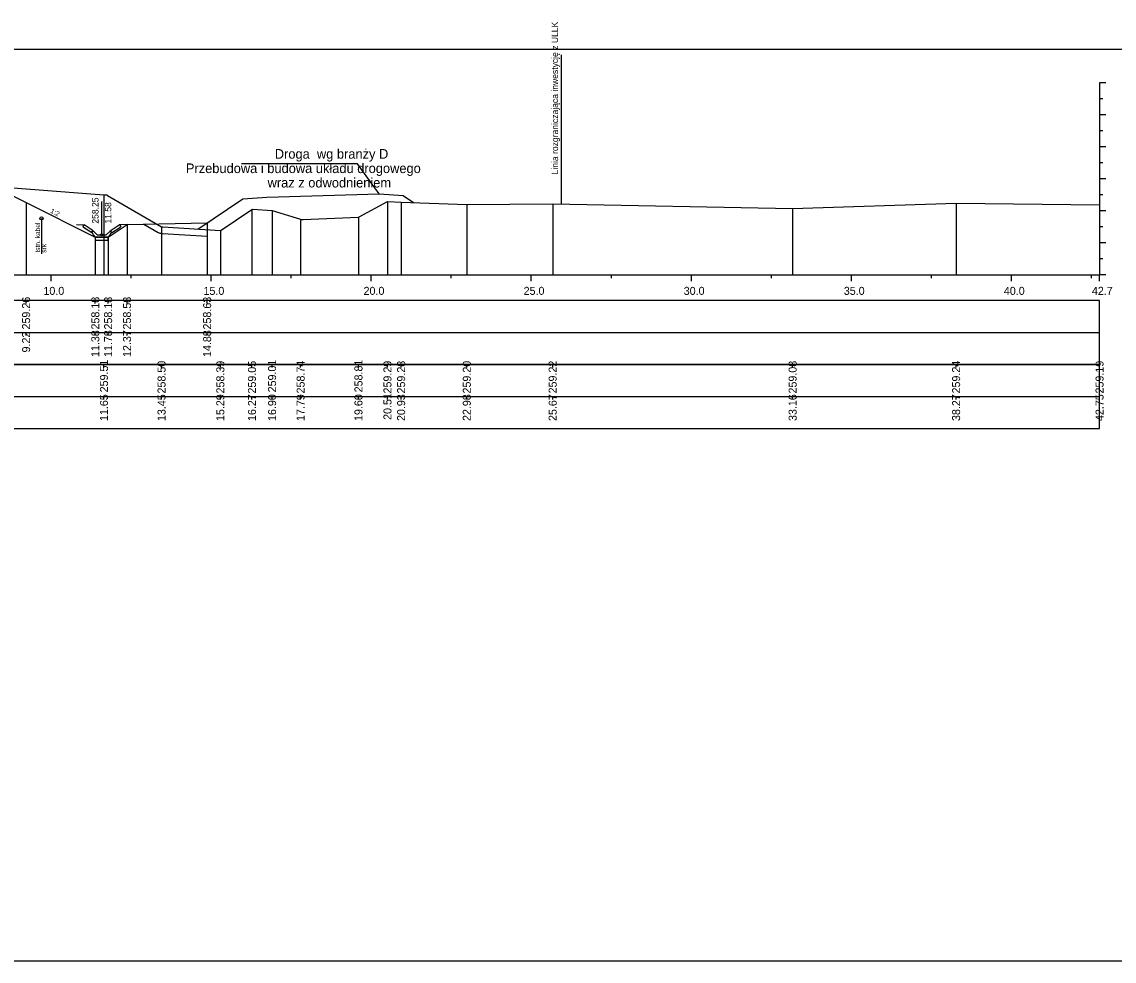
# Model space of a CAD drawing. Extents: x 6516023 to 6560129, y 5513077 to 5529206.
# Drawn here: x 6517319.3 to 6517353.42, y 5514518.16 to 5514547.51 of the extents above; entities that cross this region are included whole.
import ezdxf

# ---------------------------------------------------------------- set-up
doc = ezdxf.new("R2010")
doc.units = 0
for name, color, linetype in [('IR_default', 7, 'Continuous'), ('TOR_PRZEK_P-inne branze', 7, 'Continuous'), ('TOR_PRZEK_P-kable', 7, 'Continuous'), ('TOR_PRZEK_P-odwodnienie', 7, 'Continuous'), ('TOR_PRZEK_P-opisy', 7, 'Continuous'), ('TOR_PRZEK_P-tabelka istniejace', 7, 'Continuous'), ('TOR_PRZEK_P-tabelka projektowane', 7, 'Continuous'), ('TOR_PRZEK_P-teren istniejacy', 7, 'Continuous'), ('TOR_PRZEK_P-uklad odniesienia', 7, 'Continuous'), ('TOR_PRZEK_P-warstwa ochronna II', 7, 'Continuous'), ('TOR_PS_T-granica PKP-projektowana', 7, 'Continuous'), ('TOR_PS_T-skarpy projektowane', 7, 'Continuous'), ('TOR_RAMKI-ramka+tabelka 1', 7, 'Continuous')]:
    doc.layers.add(name, color=color, linetype=linetype)

msp = doc.modelspace()

# ---------------------------------------------------------------- linework, layer by layer
at = {"layer": 'IR_default'}
msp.add_lwpolyline([(6517303.963, 5514543.245), (6517307.463, 5514543.246), (6517308.463, 5514543.246), (6517311.963, 5514543.246), (6517312.513, 5514543.247), (6517316.013, 5514543.247), (6517317.359, 5514542.35), (6517318.563, 5514542.302), (6517319.433, 5514541.867), (6517321.593, 5514540.787), (6517321.993, 5514540.787), (6517322.586, 5514541.181), (6517325.088, 5514541.231)], dxfattribs=at)
at = {"layer": 'TOR_PRZEK_P-inne branze'}
for p, q in [((6517329.781, 5514543.077), (6517326.157, 5514543.077)), ((6517330.457, 5514542.142), (6517329.781, 5514543.077))]:
    msp.add_line(p, q, dxfattribs=at)
msp.add_lwpolyline([(6517324.795, 5514541.036), (6517326.207, 5514541.977), (6517326.957, 5514542.037), (6517328.707, 5514542.09), (6517330.457, 5514542.142), (6517331.207, 5514542.082), (6517331.532, 5514541.866)], dxfattribs=at)
at = {"layer": 'TOR_PRZEK_P-kable'}
msp.add_line((6517319.915, 5514541.372), (6517319.915, 5514540.262), dxfattribs=at)
msp.add_circle((6517319.915, 5514541.372), 0.05, dxfattribs=at)
at = {"layer": 'TOR_PRZEK_P-odwodnienie'}
for p, q in [((6517321.795, 5514540.857), (6517321.795, 5514541.901)), ((6517321.486, 5514540.916), (6517321.225, 5514541.09)), ((6517321.53, 5514540.983), (6517321.25, 5514541.17)), ((6517321.497, 5514540.933), (6517321.486, 5514540.916)), ((6517321.487, 5514540.952), (6517321.535, 5514540.976)), ((6517321.53, 5514540.983), (6517321.522, 5514540.97)), ((6517321.655, 5514540.857), (6517321.535, 5514540.976)), ((6517321.655, 5514540.857), (6517321.935, 5514540.857)), ((6517321.935, 5514540.857), (6517322.055, 5514540.976)), ((6517322.055, 5514540.976), (6517322.102, 5514540.952)), ((6517322.059, 5514540.983), (6517322.34, 5514541.17)), ((6517322.059, 5514540.983), (6517322.068, 5514540.97)), ((6517322.093, 5514540.933), (6517322.104, 5514540.916)), ((6517322.104, 5514540.916), (6517322.365, 5514541.09)), ((6517321.605, 5514540.787), (6517321.985, 5514540.787))]:
    msp.add_line(p, q, dxfattribs=at)
for points in [[(6517321.003, 5514541.181), (6517321.25, 5514541.17)], [(6517321.2, 5514541.143), (6517321.25, 5514541.17)], [(6517321.2, 5514541.143), (6517321.225, 5514541.09)], [(6517321.522, 5514540.97), (6517321.487, 5514540.952)], [(6517321.535, 5514540.857), (6517321.487, 5514540.952)], [(6517321.487, 5514540.952), (6517321.497, 5514540.933)], [(6517321.605, 5514540.787), (6517321.535, 5514540.857)], [(6517321.985, 5514540.787), (6517322.055, 5514540.857)], [(6517322.055, 5514540.857), (6517322.102, 5514540.952)], [(6517322.068, 5514540.97), (6517322.103, 5514540.952)], [(6517322.103, 5514540.952), (6517322.093, 5514540.933)], [(6517322.586, 5514541.181), (6517322.34, 5514541.17)], [(6517322.39, 5514541.143), (6517322.34, 5514541.17)], [(6517322.39, 5514541.143), (6517322.365, 5514541.09)], [(6517321.593, 5514540.787), (6517321.593, 5514540.787), (6517321.593, 5514540.787), (6517321.593, 5514540.786), (6517321.593, 5514540.787), (6517321.594, 5514540.786), (6517321.593, 5514540.787), (6517321.594, 5514540.787)], [(6517321.594, 5514540.787), (6517321.594, 5514540.788), (6517321.594, 5514540.787), (6517321.594, 5514540.787), (6517321.594, 5514540.787), (6517321.595, 5514540.787), (6517321.594, 5514540.787), (6517321.595, 5514540.788)], [(6517321.995, 5514540.787), (6517321.595, 5514540.787), (6517321.595, 5514540.687), (6517321.995, 5514540.687), (6517321.995, 5514540.787)], [(6517321.994, 5514540.787), (6517321.993, 5514540.788), (6517321.994, 5514540.787), (6517321.993, 5514540.787), (6517321.994, 5514540.787), (6517321.994, 5514540.787), (6517321.994, 5514540.787), (6517321.994, 5514540.788)], [(6517321.993, 5514540.787), (6517321.993, 5514540.787), (6517321.993, 5514540.787), (6517321.993, 5514540.786), (6517321.993, 5514540.787), (6517321.994, 5514540.786), (6517321.993, 5514540.787), (6517321.994, 5514540.787)]]:
    msp.add_lwpolyline(points, dxfattribs=at)
msp.add_circle((6517321.795, 5514540.857), 0.035, dxfattribs=at)
at = {"layer": 'TOR_PRZEK_P-tabelka istniejace'}
for p, q in [((6517321.865, 5514536.706), (6517321.865, 5514536.806)), ((6517323.664, 5514536.706), (6517323.664, 5514536.806)), ((6517325.5, 5514536.706), (6517325.5, 5514536.806)), ((6517326.488, 5514536.706), (6517326.488, 5514536.806)), ((6517327.116, 5514536.706), (6517327.116, 5514536.806)), ((6517328.008, 5514536.706), (6517328.008, 5514536.806)), ((6517329.815, 5514536.706), (6517329.815, 5514536.806)), ((6517330.72, 5514536.706), (6517330.72, 5514536.806)), ((6517331.147, 5514536.706), (6517331.147, 5514536.806)), ((6517333.198, 5514536.706), (6517333.198, 5514536.806)), ((6517335.881, 5514536.706), (6517335.881, 5514536.806)), ((6517343.376, 5514536.706), (6517343.376, 5514536.806)), ((6517348.482, 5514536.706), (6517348.482, 5514536.806)), ((6517352.963, 5514536.706), (6517352.963, 5514536.806)), ((6517269.163, 5514535.806), (6517352.963, 5514535.806)), ((6517321.865, 5514535.706), (6517321.865, 5514535.806)), ((6517323.664, 5514535.706), (6517323.664, 5514535.806)), ((6517325.5, 5514535.706), (6517325.5, 5514535.806)), ((6517326.488, 5514535.706), (6517326.488, 5514535.806)), ((6517327.116, 5514535.706), (6517327.116, 5514535.806)), ((6517328.008, 5514535.706), (6517328.008, 5514535.806)), ((6517329.815, 5514535.706), (6517329.815, 5514535.806)), ((6517330.72, 5514535.706), (6517330.72, 5514535.806)), ((6517331.147, 5514535.706), (6517331.147, 5514535.806)), ((6517333.198, 5514535.706), (6517333.198, 5514535.806)), ((6517335.881, 5514535.706), (6517335.881, 5514535.806)), ((6517343.376, 5514535.706), (6517343.376, 5514535.806)), ((6517348.482, 5514535.706), (6517348.482, 5514535.806)), ((6517352.963, 5514535.706), (6517352.963, 5514535.806))]:
    msp.add_line(p, q, dxfattribs=at)
for points in [[(6517321.865, 5514542.111), (6517321.865, 5514539.806), (6517321.865, 5514539.676), (6517321.865, 5514539.606)], [(6517330.72, 5514541.897), (6517330.72, 5514539.806), (6517330.72, 5514539.676), (6517330.72, 5514539.606)], [(6517331.147, 5514541.881), (6517331.147, 5514539.806), (6517331.147, 5514539.676), (6517331.147, 5514539.606)], [(6517326.488, 5514541.653), (6517326.488, 5514539.806), (6517326.488, 5514539.676), (6517326.488, 5514539.606)], [(6517327.116, 5514541.615), (6517327.116, 5514539.806), (6517327.116, 5514539.676), (6517327.116, 5514539.606)], [(6517333.198, 5514541.801), (6517333.198, 5514539.806), (6517333.198, 5514539.676), (6517333.198, 5514539.606)], [(6517335.881, 5514541.829), (6517335.881, 5514539.806), (6517335.881, 5514539.676), (6517335.881, 5514539.606)], [(6517343.376, 5514541.681), (6517343.376, 5514539.806), (6517343.376, 5514539.676), (6517343.376, 5514539.606)], [(6517348.482, 5514541.851), (6517348.482, 5514539.806), (6517348.482, 5514539.676), (6517348.482, 5514539.606)], [(6517352.963, 5514541.796), (6517352.963, 5514539.806), (6517352.963, 5514539.676), (6517352.963, 5514539.606)], [(6517328.008, 5514541.345), (6517328.008, 5514539.806), (6517328.008, 5514539.676), (6517328.008, 5514539.606)], [(6517329.815, 5514541.412), (6517329.815, 5514539.806), (6517329.815, 5514539.676), (6517329.815, 5514539.606)], [(6517323.664, 5514541.102), (6517323.664, 5514539.806), (6517323.664, 5514539.676), (6517323.664, 5514539.606)], [(6517325.5, 5514540.993), (6517325.5, 5514539.806), (6517325.5, 5514539.676), (6517325.5, 5514539.606)]]:
    msp.add_lwpolyline(points, dxfattribs=at)
msp.add_lwpolyline([(6517269.163, 5514536.806), (6517269.163, 5514534.806), (6517352.963, 5514534.806), (6517352.963, 5514536.806)], close=True, dxfattribs=at)
at = {"layer": 'TOR_PRZEK_P-tabelka projektowane'}
for p, q in [((6517319.433, 5514538.706), (6517319.433, 5514538.806)), ((6517321.595, 5514538.706), (6517321.595, 5514538.806)), ((6517321.995, 5514538.706), (6517321.995, 5514538.806)), ((6517322.586, 5514538.706), (6517322.586, 5514538.806)), ((6517325.088, 5514538.706), (6517325.088, 5514538.806)), ((6517269.163, 5514537.806), (6517352.963, 5514537.806)), ((6517319.433, 5514537.706), (6517319.433, 5514537.806)), ((6517321.595, 5514537.706), (6517321.595, 5514537.806)), ((6517321.995, 5514537.706), (6517321.995, 5514537.806)), ((6517322.586, 5514537.706), (6517322.586, 5514537.806)), ((6517325.088, 5514537.706), (6517325.088, 5514537.806))]:
    msp.add_line(p, q, dxfattribs=at)
for points in [[(6517319.433, 5514541.867), (6517319.433, 5514539.806), (6517319.433, 5514539.676), (6517319.433, 5514539.606)], [(6517325.088, 5514541.231), (6517325.088, 5514539.806), (6517325.088, 5514539.676), (6517325.088, 5514539.606)], [(6517322.586, 5514541.181), (6517322.586, 5514539.806), (6517322.586, 5514539.676), (6517322.586, 5514539.606)], [(6517321.595, 5514540.787), (6517321.595, 5514539.806), (6517321.595, 5514539.676), (6517321.595, 5514539.606)], [(6517321.995, 5514540.787), (6517321.995, 5514539.806), (6517321.995, 5514539.676), (6517321.995, 5514539.606)]]:
    msp.add_lwpolyline(points, dxfattribs=at)
msp.add_lwpolyline([(6517269.163, 5514538.806), (6517269.163, 5514536.806), (6517352.963, 5514536.806), (6517352.963, 5514538.806)], close=True, dxfattribs=at)
at = {"layer": 'TOR_PRZEK_P-teren istniejacy'}
msp.add_lwpolyline([(6517317.131, 5514542.476), (6517321.865, 5514542.111), (6517321.95, 5514542.106), (6517321.977, 5514542.086), (6517323.664, 5514541.102), (6517323.704, 5514541.102), (6517325.5, 5514540.993), (6517325.523, 5514541.005), (6517326.488, 5514541.653), (6517326.505, 5514541.657), (6517327.116, 5514541.615), (6517328.008, 5514541.345), (6517328.025, 5514541.334), (6517328.083, 5514541.338), (6517329.815, 5514541.412), (6517329.835, 5514541.421), (6517330.72, 5514541.897), (6517331.147, 5514541.881), (6517333.198, 5514541.801), (6517335.881, 5514541.829), (6517343.376, 5514541.681), (6517348.482, 5514541.851), (6517352.963, 5514541.796)], dxfattribs=at)
at = {"layer": 'TOR_PRZEK_P-uklad odniesienia'}
for p, q in [((6517352.963, 5514545.606), (6517352.963, 5514539.606)), ((6517353.163, 5514545.606), (6517352.963, 5514545.606)), ((6517353.063, 5514545.106), (6517352.963, 5514545.106)), ((6517353.163, 5514544.606), (6517352.963, 5514544.606)), ((6517353.063, 5514544.106), (6517352.963, 5514544.106)), ((6517353.163, 5514543.606), (6517352.963, 5514543.606)), ((6517353.063, 5514543.106), (6517352.963, 5514543.106)), ((6517353.163, 5514542.606), (6517352.963, 5514542.606)), ((6517353.063, 5514542.106), (6517352.963, 5514542.106)), ((6517353.163, 5514541.606), (6517352.963, 5514541.606)), ((6517353.063, 5514541.106), (6517352.963, 5514541.106)), ((6517353.163, 5514540.606), (6517352.963, 5514540.606)), ((6517353.063, 5514540.106), (6517352.963, 5514540.106)), ((6517272.963, 5514539.606), (6517352.963, 5514539.606)), ((6517320.213, 5514539.406), (6517320.213, 5514539.606)), ((6517322.713, 5514539.506), (6517322.713, 5514539.606)), ((6517325.213, 5514539.406), (6517325.213, 5514539.606)), ((6517327.713, 5514539.506), (6517327.713, 5514539.606)), ((6517330.213, 5514539.406), (6517330.213, 5514539.606)), ((6517332.713, 5514539.506), (6517332.713, 5514539.606)), ((6517335.213, 5514539.406), (6517335.213, 5514539.606)), ((6517337.713, 5514539.506), (6517337.713, 5514539.606)), ((6517340.213, 5514539.406), (6517340.213, 5514539.606)), ((6517342.713, 5514539.506), (6517342.713, 5514539.606)), ((6517345.213, 5514539.406), (6517345.213, 5514539.606)), ((6517347.713, 5514539.506), (6517347.713, 5514539.606)), ((6517350.213, 5514539.406), (6517350.213, 5514539.606)), ((6517352.713, 5514539.506), (6517352.713, 5514539.606)), ((6517352.963, 5514539.406), (6517352.963, 5514539.606)), ((6517353.163, 5514539.606), (6517352.963, 5514539.606))]:
    msp.add_line(p, q, dxfattribs=at)
at = {"layer": 'TOR_PRZEK_P-warstwa ochronna II'}
msp.add_lwpolyline([(6517318.564, 5514542.302), (6517319.433, 5514541.867), (6517321.595, 5514540.787), (6517321.995, 5514540.787), (6517322.586, 5514541.181), (6517325.088, 5514541.231)], dxfattribs=at)
at = {"layer": 'TOR_PS_T-granica PKP-projektowana'}
msp.add_line((6517336.161, 5514541.823), (6517336.161, 5514546.481), dxfattribs=at)
at = {"layer": 'TOR_PS_T-skarpy projektowane'}
for points in [[(6517323.113, 5514541.192), (6517323.563, 5514540.929)], [(6517323.663, 5514540.902), (6517323.697, 5514540.902), (6517325.088, 5514540.818)]]:
    msp.add_lwpolyline(points, dxfattribs=at)
msp.add_arc((6517323.664, 5514541.102), 0.2, 239.7392, 269.7985, dxfattribs=at)
at = {"layer": 'TOR_RAMKI-ramka+tabelka 1'}
msp.add_lwpolyline([(6517179.513, 5514546.656), (6517427.013, 5514546.656), (6517427.013, 5514518.156), (6517179.513, 5514518.156)], close=True, dxfattribs=at)

# ---------------------------------------------------------------- texts
at = {"layer": 'TOR_PRZEK_P-inne branze'}
for s, p in [('Droga  wg branży D', (6517327.201, 5514543.237)), ('Przebudowa i budowa układu drogowego', (6517324.424, 5514542.787)), ('wraz z odwodnieniem ', (6517326.976, 5514542.337))]:
    msp.add_text(s, height=0.3, dxfattribs=at).set_placement(p)
at = {"layer": 'TOR_PRZEK_P-kable'}
for s, height, p in [('Istn. kabel', 0.14999, (6517319.87, 5514540.298)), ('srk', 0.15, (6517320.064, 5514540.298))]:
    msp.add_text(s, height=height, rotation=90.0511, dxfattribs=at).set_placement(p)
at = {"layer": 'TOR_PRZEK_P-odwodnienie'}
for s, p in [('258.25', (6517321.695, 5514541.207)), ('11.58', (6517322.095, 5514541.207))]:
    msp.add_text(s, height=0.2, rotation=90, dxfattribs=at).set_placement(p)
at = {"layer": 'TOR_PRZEK_P-opisy'}
msp.add_text('1:2', height=0.15, rotation=332.9299, dxfattribs=at).set_placement((6517320.176, 5514541.557))
at = {"layer": 'TOR_PRZEK_P-tabelka istniejace'}
for s, p in [('259.51', (6517321.99, 5514535.933)), ('258.50', (6517323.789, 5514535.898)), ('258.39', (6517325.625, 5514535.898)), ('259.05', (6517326.613, 5514535.897)), ('259.01', (6517327.241, 5514535.933)), ('258.74', (6517328.133, 5514535.899)), ('258.81', (6517329.94, 5514535.933)), ('259.29', (6517330.845, 5514535.898)), ('259.28', (6517331.272, 5514535.898)), ('259.20', (6517333.323, 5514535.898)), ('259.22', (6517336.006, 5514535.9)), ('259.08', (6517343.501, 5514535.898)), ('259.24', (6517348.607, 5514535.899)), ('259.19', (6517353.088, 5514535.898)), ('11.65', (6517321.99, 5514535.037)), ('13.45', (6517323.789, 5514535.037)), ('15.29', (6517325.625, 5514535.038)), ('16.27', (6517326.613, 5514535.038)), ('16.90', (6517327.241, 5514535.038)), ('17.79', (6517328.133, 5514535.038)), ('19.60', (6517329.94, 5514535.038)), ('20.51', (6517330.845, 5514535.073)), ('20.93', (6517331.272, 5514535.038)), ('22.98', (6517333.323, 5514535.038)), ('25.67', (6517336.006, 5514535.038)), ('33.16', (6517343.501, 5514535.038)), ('38.27', (6517348.607, 5514535.038)), ('42.75', (6517353.088, 5514535.037))]:
    msp.add_text(s, height=0.25, rotation=90, dxfattribs=at).set_placement(p)
at = {"layer": 'TOR_PRZEK_P-tabelka projektowane'}
for s, p in [('259.26', (6517319.558, 5514537.898)), ('258.18', (6517321.72, 5514537.898)), ('258.18', (6517322.12, 5514537.898)), ('258.58', (6517322.711, 5514537.898)), ('258.63', (6517325.213, 5514537.898)), ('9.22', (6517319.558, 5514537.18)), ('11.38', (6517321.72, 5514537.038)), ('11.78', (6517322.12, 5514537.038)), ('12.37', (6517322.711, 5514537.038)), ('14.88', (6517325.213, 5514537.038))]:
    msp.add_text(s, height=0.25, rotation=90, dxfattribs=at).set_placement(p)
at = {"layer": 'TOR_PRZEK_P-uklad odniesienia'}
for s, p in [('10.0', (6517319.974, 5514538.981)), ('15.0', (6517324.974, 5514538.981)), ('20.0', (6517329.974, 5514538.981)), ('25.0', (6517334.974, 5514538.981)), ('30.0', (6517339.974, 5514538.981)), ('35.0', (6517344.974, 5514538.981)), ('40.0', (6517349.974, 5514538.981)), ('42.7', (6517352.724, 5514538.981))]:
    msp.add_text(s, height=0.25, dxfattribs=at).set_placement(p)
at = {"layer": 'TOR_PS_T-granica PKP-projektowana'}
msp.add_text('Linia rozgraniczająca inwestycję z ULLK', height=0.2, rotation=90.0511, dxfattribs=at).set_placement((6517336.051, 5514542.745))

doc.saveas('drawing.dxf')
